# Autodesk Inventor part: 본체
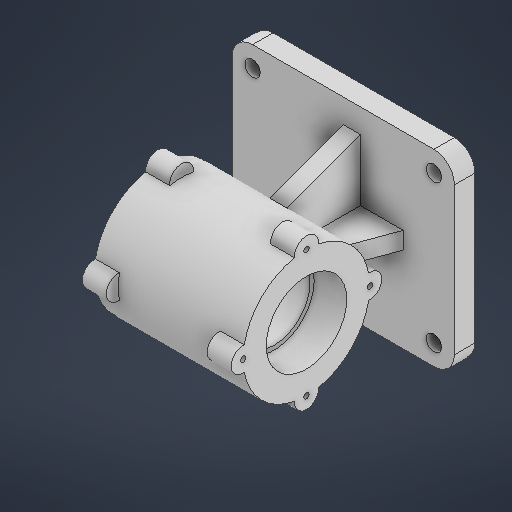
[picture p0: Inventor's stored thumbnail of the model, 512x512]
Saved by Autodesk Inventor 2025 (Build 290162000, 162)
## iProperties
Created: 2025-08
Part Number: 본체
Material: 일반
Document SubType Name: Modeling
Designer: infra11
Density: 1 g/cm^3
Appearance: 기본값
Author: infra11
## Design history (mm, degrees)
sketch "스케치1"
  geometry: L1 (-65, -55)-(65, -55); L2 (65, -55)-(65, 55); L3 (65, 55)-(-65, 55); L4 (-65, 55)-(-65, -55); L5 (-65, -55)-(65, 55); L6 (65, -55)-(-65, 55); 1 further point
  constraints: 12 end point, 2 midpoint, 2 parallel, 1 horizontal, 1 perpendicular
  dimensions: "d0" = 130 distance of L2.end L3.end; "d1" = 110 distance of L1.end L2.end
extrude "돌출1" new body sketch "스케치1" stored distance "d2" = 12; taper "d3" = 0 deg
sketch "스케치2"
  geometry: L1 (-53, -43)-(53, -43); L2 (53, -43)-(53, 43); L3 (53, 43)-(-53, 43); L4 (-53, 43)-(-53, -43); L5 (-53, -43)-(53, 43); L6 (53, -43)-(-53, 43); C1 r 4.5 at (-53, 43); C2 r 4.5 at (53, 43); C3 r 4.5 at (-53, -43); C4 r 4.5 at (53, -43); 1 further point
  constraints: 12 end point, 4 centre point, 4 coincident, 2 midpoint, 2 parallel, 1 horizontal, 1 perpendicular
  dimensions: "d4" = 106 distance of L2.end L3.end; "d5" = 86 distance of L1.end L2.end; "d6" = 9 diameter of C1; "d7" = 9 diameter of C3; "d8" = 9 diameter of C4; "d9" = 9 diameter of C2
extrude "돌출2" cut sketch "스케치2" extent not by distance; stored distance "d10" = 0; taper "d11" = 0 deg
sketch "스케치3"
  geometry: 1 further point
sketch "스케치4"
  geometry: L1 (38.5, 113)-(-48.5, 113); L2 (-48.5, 113)-(-48.5, 99.5); L3 (-48.5, 99.5)-(-29.5, 99.5); L4 (-29.5, 99.5)-(-29.5, 97); L5 (-29.5, 97)-(19.5, 97); L6 (19.5, 97)-(19.5, 99.5); L7 (19.5, 99.5)-(38.5, 99.5); L8 (38.5, 99.5)-(38.5, 113); L9 (-65, -6)-(65, -6) reference; L10 (38.5, 106.25)-(-5, 106.25); L11 (84.032, 76)-(-73.458, 76); 2 further points
  constraints: 20 end point, 6 perpendicular, 2 horizontal, 2 point on line, 1 midpoint, 1 parallel
  dimensions: "d12" = 2.5 distance of L4.end L3.end; "d13" = 2.5 distance of L5.end L6.end (derived); "d14" = 87 distance of L1.start L1.end; "d15" = 19 distance of L6.end L7.end; "d16" = 19 distance of L2.end L3.end; "d19" = 43.5 distance of L10.start L10.end; "d20" = 70 horizontal distance of point (65, 6) L10.end; "d22" = 21 distance between parallel lines of L11 L5 (derived); "d23" = 82 distance between parallel lines of L9 L11; "d24" = 23.5 distance between parallel lines of L11 L7; "d25" = 23.5 distance between parallel lines of L11 L3 (derived); "d26" = 37 distance between parallel lines of L11 L1
revolve "회전1" sketch "스케치4" stored, may be unused: angle "d27" = 90 deg
sketch "스케치5"
  geometry: L1 (-65, 6)-(65, 6); L2 (-35, 6)-(-22.989, 39); L3 (38.5, 39)-(-48.5, 39) reference; L4 (12.663, 39.895)-(25, 6); L5 (-65, 6)-(65, 6) reference; L6 (-35, 6)-(25, 6); L7 (-5, 6)-(-65, 6); L8 (12.989, 39)-(-22.989, 39); 2 further points
  constraints: 12 end point, 5 point on line, 3 collinear, 1 coincident, 1 midpoint
  dimensions: "d28" = 60 distance of L4.end L2.start; "d29" = 70 deg angle of L1 L2; "d30" = 70 deg angle of L1 L4; "d48" = 70 distance of L1.end point (-5, 6)
sketch "스케치6"
  geometry: C1 r 7 at (37, 0); C2 r 7 at (0, 37); C3 r 7 at (-37, 0); C4 r 7 at (0, -37); C5 r 23.5 at (0, 0) reference; A1 r 37 centre (0, 0) between (37, 0) and (0, 37); 4 further points
  constraints: 6 coincident, 5 centre point, 4 point on circle, 2 horizontal alignment, 2 vertical alignment
  dimensions: "d33" = 74 diameter of A1; "d34" = 14 diameter of C2; "d35" = 14 diameter of C1; "d36" = 14 diameter of C4; "d37" = 14 diameter of C3
extrude "돌출3" join sketch "스케치6" distance "d38" = 14; taper "d39" = 0 deg
sketch "스케치7" dims "d40" = 74
  geometry: L1 (-37, 44)-(-37, -37); L2 (7, 0)-(-81, 0); C1 r 23.5 at (-37, 0) reference; A1 r 7 centre (-37, 37) between (-30.031, 36.338) and (-43.969, 36.338) reference; A2 r 7 centre (-37, -37) between (-43.969, -36.338) and (-30.031, -36.338) reference; A3 r 37 centre (-37, 0) between (-43.969, 36.338) and (-30.031, 36.338) reference; A4 r 7 centre (0, 0) between (-0.662, -6.969) and (-0.662, 6.969) reference; A5 r 7 centre (-74, 0) between (-73.338, 6.969) and (-73.338, -6.969) reference; 2 further points
  constraints: 4 end point, 3 point on circle, 1 coincident, 1 horizontal, 1 vertical, 2 other
hole "구멍1" sketch "스케치7" at (0, 0), (-37, -37), (-37, 37), (-74, 0) diameter "d41" = 3.242; stored, may be unused: countersink angle "d45" = 90 deg, drill point angle "d47" = 118 deg; dims "d42" = 8, "d43" = 4, "d44" = 2, "d46" = 10
sketch "스케치8"
  geometry: 1 further point
extrude "돌출4" join sketch "스케치5" stored distance "d49" = 10; taper "d50" = 0 deg
sketch "스케치9"
  geometry: 1 further point
node "작업 평면1"
sketch "스케치10"
  geometry: L1 (-25.336, 49.036)-(-41, 6); L2 (-47.5, 6)-(-38.5, 6) reference; L3 (55, 6)-(-55, 6) reference; 2 further points
  constraints: 2 end point, 1 point on line, 2 other
  dimensions: "d52" = 70 deg angle of L3 L1; "d53" = 14 distance of L3.end L1.end
feature "리브1" sketch "스케치10" dims "d54" = 10, "d55" = 10, "d56" = 0, "d57" = 0, "d58" = 1, "d59" = 1
sketch "스케치11"
  geometry: C1 r 7 at (-37, 0); C2 r 7 at (0, -37); C3 r 7 at (0, 37); C4 r 7 at (37, 0); A1 r 37 centre (0, 0) between (-36.338, 6.969) and (-36.338, -6.969) reference; A2 r 7 centre (-37, 0) between (-36.338, 6.969) and (-36.338, -6.969) reference; 4 further points
  constraints: 4 centre point, 4 coincident
  dimensions: "d60" = 7 radius of A2 (derived); "d61" = 14 diameter of C2; "d62" = 14 diameter of C3; "d63" = 14 diameter of C4; "d74" = 14 diameter of C1
extrude "돌출5" join sketch "스케치11" distance "d64" = 14; taper "d65" = 0 deg
sketch "스케치12"
  geometry: A1 r 37 centre (-37, 0) between (-73.338, -6.969) and (-43.969, -36.338) reference; A2 r 7 centre (-74, 0) between (-73.338, 6.969) and (-73.338, -6.969) reference; A3 r 7 centre (-37, -37) between (-43.969, -36.338) and (-30.031, -36.338) reference; A4 r 7 centre (0, 0) between (-0.662, -6.969) and (-0.662, 6.969) reference; A5 r 7 centre (-37, 37) between (-30.031, 36.338) and (-43.969, 36.338) reference; 1 further point
hole "구멍2" sketch "스케치12" at (-74, 0), (-37, -37), (0, 0), (-37, 37) diameter "d66" = 3.242; stored, may be unused: countersink angle "d70" = 90 deg, drill point angle "d72" = 118 deg; dims "d67" = 8, "d68" = 4, "d69" = 2, "d71" = 10
fillet "모깎기1" dims "d73" = 12
node "솔리드1"
mirror "미러1"
feature "A9D066F2-1C7D-4E18-AEED-F7BC21143FA4" dims "d41" = 3.242, "d42" = 8, "d43" = 4, "d44" = 2, "d45" = 90 deg, "d46" = 10, "d47" = 118 deg
other parameters: "d51" = 5
